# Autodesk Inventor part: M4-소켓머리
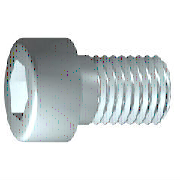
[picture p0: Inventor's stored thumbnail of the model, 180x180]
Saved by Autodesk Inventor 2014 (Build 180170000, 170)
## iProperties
IsCustomPart: 0
Created: 2009-02
Part Number: M4-소켓머리
Material: 강, 연강
Description: 6각머리 태핑 나사
Document SubType Name: Modeling
Standard: KS B 1003
Designer: 한국산업디자인학원 [http://gmhk.co.kr]
Standards Organization: KS
Language: ko-KR
Size Designation: M 4 x 12
Categories: <MemberInstance><Categories><Category DisplayName="조임쇠" InternalName="e4da775c-781d-43d5-af7c-5136215cf5a6" Mnemonic="FSTN"><Category DisplayName="볼트" InternalN
Density: 7.86 g/cm^3
Appearance: _시험-금속-강(연마)
Mass: 2.23465 g
Surface Area: 3.30853 cm^2
Volume: 0.284306 cm^3
Author: pww
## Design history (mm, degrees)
sketch "스케치1"
  geometry: L1 (-1, 0)-(12, 0); L2 (12, 0)-(12, 2); L3 (12, 2)-(1.75, 2); L4 (1.75, 2)-(1.32, 2); L5 (1.32, 2)-(0, 2); L6 (0, 2)-(0, 3.5); L7 (0, 3.5)-(-4, 3.5); L8 (-4, 3.5)-(-4, 1.732); L9 (-4, 1.732)-(-2, 1.732); L10 (-2, 1.732)-(-1, 0); L11 (-7.2, 0)-(15.2, 0) reference; L12 (0, -0.7)-(0, 4.2) reference; L13 (1.75, 2)-(0, 2)
  constraints: 22 end point, 6 parallel, 2 collinear, 2 perpendicular, 1 horizontal, 1 point on line
  dimensions: "d1" = 10.25 distance from line of L3.end L2 (= GEL); "d2" = 0.42952 distance of L4.end L3.end (computed from GAL); "d3" = 4 distance between parallel lines of L8 L6 (= KOH); "d4" = 2 distance of L8.end L9.end (= INTI); "d5" = 60 deg angle of L10 L1; "d6" = 4 diameter of L3 L1 (= GD); "d7" = 4 diameter of L5 L1 (= BDM); "d8" = 3.4641 diameter of L9 L1 (= 1.1547 x SW); "d9" = 7 diameter of L7 L1 (= KOD); "d26" = 12 distance between parallel lines of L12 L2 (= NLG)
revolve "본체" sketch "스케치1" stored, may be unused: angle "d10" = 90 deg
sketch "스케치2"
  geometry: L1 (0, -4.9)-(0, 4.9) reference; L2 (-4.9, 0)-(4.9, 0) reference; L3 (1.732, 0)-(0.866, -1.5); L4 (0.866, -1.5)-(-0.866, -1.5); L5 (-0.866, -1.5)-(-1.732, 0); L6 (-1.732, 0)-(-0.866, 1.5); L7 (-0.866, 1.5)-(0.866, 1.5); L8 (0.866, 1.5)-(1.732, 0); 2 further points
  constraints: 12 end point, 1 coincident, 1 horizontal alignment, 1 point on line, 12 other
extrude "슬롯" join sketch "스케치2" stored distance "d11" = 10; taper "d12" = 0 deg
workplane "Work Plane1"
fillet "Fillet2" dims "d30" = 0.1 (= R)
body "Solid1"
fillet "모깎기1" dims "d17" = 0.4 (= RR)
feature "스레드" dims "d13" = 10.25 (= GEL), "d14" = 0
chamfer "모따기1" distance "d15" = 0.42941 (= -0.5 x SPD + 0.5 x GD); stored, may be unused: second distance "d16" = 0.42941 (= GUL), angle "d27" = 45 deg
other parameters: "GD" = 4 (= NND) [user parameter; used in 2 equation terms], "NLG" = 12 [user parameter; used in 1 equation term], "GEL" = 10.25 [user parameter; used in 2 equation terms], "KOD" = 7 [user parameter; used in 1 equation term], "KOH" = 4 [user parameter; used in 1 equation term], "INTI" = 2 [user parameter; used in 1 equation term], "GAL" = 0.42941 (= 0.61345 x PTC) [user parameter; used in 1 equation term], "GUL" = 0.42941 (= 0.61345 x PTC) [user parameter; used in 1 equation term], "BDM" = 4 (= NND) [user parameter; used in 1 equation term], "SW" = 3 [user parameter; used in 2 equation terms], "RR" = 0.4 [user parameter; used in 1 equation term], "SPD" = 3.14117 (= NND - 1.2269 x PTC) [user parameter; used in 1 equation term], "d19" = 0, "d28" = 0, "d29" = 0, "R" = 0.1 [user parameter; used in 1 equation term], "PHH" = 0.2 [user parameter], "GD1" = 3.14117 (= THREADDIA - 1.2269 x PTC) [user parameter], "THREADDIA" = 4 [user parameter; used in 1 equation term], "FAWI" = 45 deg [user parameter], "TPU" = 14.28571 (computed from PTC) [user parameter], "PTC" = 0.7 [user parameter; used in 5 equation terms], "NND" = 4 [user parameter; used in 3 equation terms], "TOA" = 30 deg [user parameter], "E0" = 3.465 (= 1.155 x SW) [user parameter]
